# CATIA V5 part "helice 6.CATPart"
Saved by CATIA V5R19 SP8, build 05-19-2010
Part number: helice 6
Bounding box of the stored display mesh (mm): x -17.321 to 17.321, y -30 to 195, z -10 to 20
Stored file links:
  G:\EU_thinkMotion\CFAO_2010\MMS_groupe2\MMS_groupe2\A reprendre\splanchenault\Planchenault\helice 6.CATPart
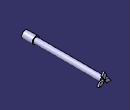
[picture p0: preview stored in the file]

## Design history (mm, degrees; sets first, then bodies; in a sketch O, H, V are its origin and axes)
Body1 (main body)
  Sketch1 on yz-plane, origin (0, 0, 0), H (0, 1, 0), V (0, 0, 1)
    line L1 (0, 0) -> (-30, 0)
    line L2 (-30, 0) -> (-30, -10)
    line L3 (-30, -10) -> (0, -10)
    point P3 (0, -10)
    line L4 (0, -10) -> (0, -7.5)
    line L5 (0, -7.5) -> (190, -7.5)
    line L6 (190, -7.5) -> (190, 0)
    line L7 (190, 0) -> (0, 0)
    length L2 = 10
    length L6 = 7.5
    length L3 = 30
    length L5 = 190
    horizontal: L1 H, L3 H, L5 H, L7 H
    vertical: L2 V, L4 V, L6 V
    coincidence: P3 V
  Shaft1: profile Sketch1, axis Sketch1.L7, angle 360
  Sketch2 on face of Shaft1 from Sketch1.L6, origin (0, 190, 0), H (-1, 0, 0), V (0, 0, 1)
    construction line L1 (27.3861, 15.8114) -> (-27.3861, -15.8114)
    axis line L2 (19.3649, -11.1803) -> (-19.3649, 11.1803)
    line L3 (0, 0) -> (5.7735, 10)
    point P5 (5.7735, 10)
    line L4 (5.7735, 10) -> (0, 20)
    point P6 (0, 20)
    line L5 (0, 20) -> (-5.7735, 10)
    point P7 (-5.7735, 10)
    line L6 (-5.7735, 10) -> (0, 0)
    point P8 (-5.7735, -10)
    point P9 (0, 0)
    line L7 (0, 0) -> (-5.7735, -10)
    point P10 (-17.3205, -10)
    line L8 (-5.7735, -10) -> (-17.3205, -10)
    point P11 (-11.547, 0)
    line L9 (-17.3205, -10) -> (-11.547, 0)
    line L10 (-11.547, 0) -> (0, 0)
    point P12 (11.547, 0)
    point P13 (0, 0)
    line L11 (0, 0) -> (11.547, 0)
    point P14 (17.3205, -10)
    line L12 (11.547, 0) -> (17.3205, -10)
    point P15 (5.7735, -10)
    line L13 (17.3205, -10) -> (5.7735, -10)
    line L14 (5.7735, -10) -> (0, 0)
    angle L1 V = 60
    angle L2 V = 60
    coincidence: L2 O, P6 V, O P9, O P13, P9 P13
    perpendicularity: L3 L2, L4 L1
    parallelism: L5 L3, L6 L4
    symmetry: P5 P8 L2, O P9 L2, L3 L7 L2, P6 P10 L2, L4 L8 L2, P7 P11 L2, L5 L9 L2, L6 L10 L2, P5 P12 L1, O P13 L1, L3 L11 L1, P6 P14 L1, L4 L12 L1, P7 P15 L1, L5 L13 L1, L6 L14 L1
  Pad1: profile Sketch2, direction (0, 1, 0), length 5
